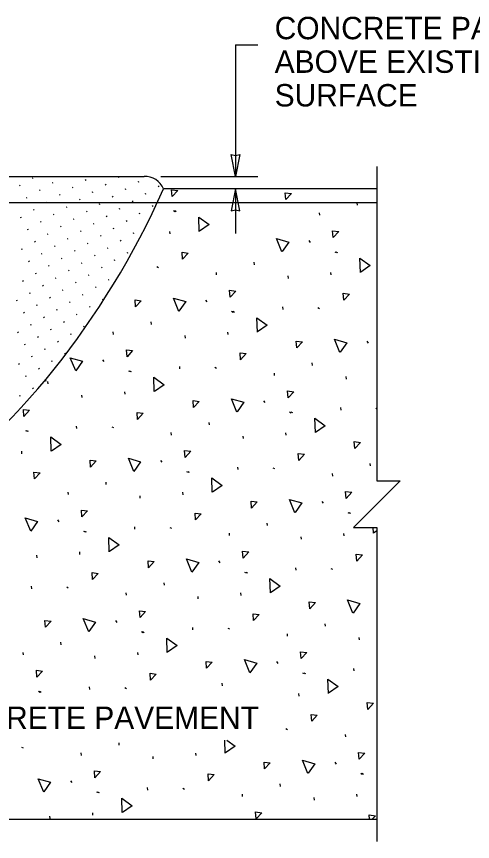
# Model space of a CAD drawing. Extents: x 99862 to 104211, y 98939 to 105076.
# Drawn here: x 102390 to 102716, y 103789 to 104378 of the extents above; entities that cross this region are included whole.
import ezdxf

# ---------------------------------------------------------------- set-up
doc = ezdxf.new("R2010")
doc.units = 0
for name, color, linetype in [('Level 1', 7, 'Continuous'), ('Level 15', 7, 'Continuous'), ('Level 20', 7, 'Continuous'), ('Level 3', 7, 'Continuous'), ('Level 4', 7, 'Continuous'), ('Level 6', 7, 'Continuous')]:
    doc.layers.add(name, color=color, linetype=linetype)

msp = doc.modelspace()

# ---------------------------------------------------------------- linework, layer by layer
at = {"layer": 'Level 1'}
for p, q in [((102106.49, 104263.53), (102481.5, 104263.53)), ((102647.84, 104254.65), (102495.44, 104254.65))]:
    msp.add_line(p, q, dxfattribs=at)
for points in [[(102647.84, 104270.65), (102647.84, 104046.13), (102664.55, 104046.13), (102631.14, 104012.73), (102647.84, 104012.73), (102647.84, 103788.62)], [(100169.63, 103804.62), (100694.77, 103804.62), (102647.84, 103804.62)]]:
    msp.add_lwpolyline(points, dxfattribs=at)
msp.add_arc((102481.79, 104248.62), 14.92, 23.84243, 91.13462, dxfattribs=at)
msp.add_ellipse((102063.85, 104535.63), major_axis=(0, -590.4), ratio=0.83118, start_param=0, end_param=1.074783, dxfattribs=at)
msp.add_ellipse((102063.85, 104535.63), major_axis=(0, -590.4), ratio=0.83118, start_param=0, end_param=1.074783, dxfattribs=at)
at = {"layer": 'Level 15'}
for p, q in [((102546.8, 104357.47), (102546.8, 104263.53)), ((102546.8, 104357.47), (102562.8, 104357.47)), ((102546.8, 104254.65), (102546.8, 104222.65))]:
    msp.add_line(p, q, dxfattribs=at)
for points in [[(102546.8, 104263.53), (102543.72, 104279.26), (102546.8, 104278.53), (102549.89, 104279.26)], [(102546.8, 104254.65), (102543.72, 104238.92), (102546.8, 104239.65), (102549.89, 104238.92)]]:
    msp.add_lwpolyline(points, close=True, dxfattribs=at)
msp.add_lwpolyline([(102493.5, 104263.53), (102537.23, 104263.53), (102562.8, 104263.53)], dxfattribs=at)
at = {"layer": 'Level 3'}
for p, q in [((102401.68, 104262.19), (102402.29, 104262.54)), ((102463.02, 104262.96), (102463.62, 104263.31)), ((102392.41, 104256.84), (102393.02, 104257.19)), ((102415.95, 104258.88), (102416.55, 104259.23)), ((102439.48, 104260.92), (102440.09, 104261.27)), ((102453.75, 104257.61), (102454.36, 104257.96)), ((102477.29, 104259.65), (102477.89, 104260)), ((102491.55, 104256.34), (102492.16, 104256.69)), ((102406.68, 104253.53), (102407.29, 104253.88)), ((102430.21, 104255.57), (102430.82, 104255.92)), ((102444.48, 104252.26), (102445.09, 104252.61)), ((102468.02, 104254.3), (102468.62, 104254.65)), ((102482.29, 104250.99), (102482.89, 104251.34)), ((102397.41, 104248.18), (102398.02, 104248.53)), ((102411.68, 104244.87), (102412.29, 104245.22)), ((102420.95, 104250.22), (102421.55, 104250.57)), ((102435.21, 104246.91), (102435.82, 104247.26)), ((102458.75, 104248.95), (102459.36, 104249.3)), ((102473.02, 104245.64), (102473.62, 104245.99)), ((102402.41, 104239.52), (102403.02, 104239.87)), ((102425.95, 104241.56), (102426.55, 104241.91)), ((102449.48, 104243.6), (102450.09, 104243.95)), ((102463.75, 104240.29), (102464.36, 104240.64)), ((102487.29, 104242.33), (102487.89, 104242.68)), ((102393.14, 104234.17), (102393.75, 104234.52)), ((102416.68, 104236.21), (102417.29, 104236.56)), ((102430.95, 104232.9), (102431.55, 104233.25)), ((102440.21, 104238.25), (102440.82, 104238.6)), ((102454.48, 104234.94), (102455.09, 104235.29)), ((102478.02, 104236.98), (102478.62, 104237.33)), ((102407.41, 104230.86), (102408.02, 104231.21)), ((102421.68, 104227.55), (102422.29, 104227.9)), ((102445.21, 104229.59), (102445.82, 104229.94)), ((102468.75, 104231.63), (102469.36, 104231.98)), ((102398.14, 104225.51), (102398.75, 104225.86)), ((102412.41, 104222.2), (102413.02, 104222.55)), ((102435.95, 104224.24), (102436.55, 104224.59)), ((102450.21, 104220.93), (102450.82, 104221.28)), ((102459.48, 104226.28), (102460.09, 104226.63)), ((102473.75, 104222.97), (102474.36, 104223.32)), ((102403.14, 104216.85), (102403.75, 104217.2)), ((102426.68, 104218.89), (102427.29, 104219.24)), ((102440.95, 104215.58), (102441.55, 104215.93)), ((102464.48, 104217.62), (102465.09, 104217.97)), ((102393.88, 104211.49), (102394.48, 104211.84)), ((102417.41, 104213.54), (102418.02, 104213.89)), ((102431.68, 104210.23), (102432.29, 104210.58)), ((102455.21, 104212.27), (102455.82, 104212.62)), ((102408.14, 104208.19), (102408.75, 104208.54)), ((102422.41, 104204.88), (102423.02, 104205.23)), ((102445.95, 104206.92), (102446.55, 104207.27)), ((102460.21, 104203.61), (102460.82, 104203.96)), ((102469.48, 104208.96), (102470.09, 104209.31)), ((102398.88, 104202.83), (102399.48, 104203.18)), ((102413.14, 104199.53), (102413.75, 104199.88)), ((102436.68, 104201.57), (102437.29, 104201.92)), ((102450.95, 104198.26), (102451.55, 104198.61)), ((102403.88, 104194.17), (102404.48, 104194.52)), ((102427.41, 104196.22), (102428.02, 104196.57)), ((102441.68, 104192.91), (102442.29, 104193.26)), ((102394.61, 104188.82), (102395.21, 104189.17)), ((102408.88, 104185.51), (102409.48, 104185.86)), ((102418.14, 104190.86), (102418.75, 104191.21)), ((102432.41, 104187.56), (102433.02, 104187.91)), ((102455.95, 104189.6), (102456.55, 104189.95)), ((102399.61, 104180.16), (102400.21, 104180.51)), ((102423.14, 104182.2), (102423.75, 104182.55)), ((102446.68, 104184.25), (102447.29, 104184.6)), ((102390.34, 104174.81), (102390.95, 104175.16)), ((102413.88, 104176.85), (102414.48, 104177.2)), ((102437.41, 104178.89), (102438.02, 104179.24)), ((102451.68, 104175.59), (102452.29, 104175.94)), ((102404.61, 104171.5), (102405.21, 104171.85)), ((102418.88, 104168.19), (102419.48, 104168.54)), ((102428.14, 104173.54), (102428.75, 104173.89)), ((102442.41, 104170.23), (102443.02, 104170.58)), ((102395.34, 104166.15), (102395.95, 104166.5)), ((102409.61, 104162.84), (102410.21, 104163.19)), ((102433.14, 104164.88), (102433.75, 104165.23)), ((102400.34, 104157.49), (102400.95, 104157.84)), ((102423.88, 104159.53), (102424.48, 104159.88)), ((102438.14, 104156.22), (102438.75, 104156.57)), ((102391.07, 104152.14), (102391.68, 104152.49)), ((102414.61, 104154.18), (102415.21, 104154.53)), ((102428.88, 104150.87), (102429.48, 104151.22)), ((102405.34, 104148.83), (102405.95, 104149.18)), ((102419.61, 104145.52), (102420.21, 104145.87)), ((102396.07, 104143.48), (102396.68, 104143.83)), ((102410.34, 104140.17), (102410.95, 104140.52)), ((102401.07, 104134.82), (102401.68, 104135.17)), ((102424.61, 104136.86), (102425.21, 104137.21)), ((102391.81, 104129.47), (102392.41, 104129.82)), ((102415.34, 104131.51), (102415.95, 104131.86)), ((102396.81, 104120.81), (102397.41, 104121.16)), ((102406.07, 104126.16), (102406.68, 104126.51)), ((102411.07, 104117.5), (102411.68, 104117.85)), ((102401.81, 104112.15), (102402.41, 104112.5)), ((102392.54, 104106.8), (102393.14, 104107.15))]:
    msp.add_line(p, q, dxfattribs=at)
at = {"layer": 'Level 4'}
for p, q in [((102634.02, 104242.98), (102633.83, 104244.72)), ((102502.55, 104239.09), (102503.7, 104238.52)), ((102503.37, 104239.09), (102504.51, 104238.52)), ((102607, 104235.79), (102606.81, 104237.53)), ((102500.05, 104222.44), (102499.87, 104224.18)), ((102599.14, 104217.69), (102600.09, 104216.4)), ((102617.71, 104209.77), (102618.85, 104209.21)), ((102618.52, 104209.78), (102619.67, 104209.21)), ((102490.55, 104199.12), (102491.7, 104198.55)), ((102560.34, 104200.44), (102560.15, 104202.18)), ((102533.32, 104193.25), (102533.13, 104194.99)), ((102584.64, 104190.68), (102584.45, 104192.42)), ((102615.21, 104193.13), (102615.03, 104194.87)), ((102525.46, 104175.15), (102526.41, 104173.86)), ((102580.8, 104168.55), (102580.62, 104170.29)), ((102605.71, 104169.81), (102606.86, 104169.24)), ((102544.03, 104167.24), (102545.18, 104166.67)), ((102544.85, 104167.24), (102545.99, 104166.67)), ((102486.66, 104157.9), (102486.48, 104159.64)), ((102459.64, 104150.71), (102459.46, 104152.45)), ((102541.54, 104150.6), (102541.35, 104152.34)), ((102510.96, 104148.14), (102510.77, 104149.88)), ((102640.62, 104145.84), (102641.57, 104144.55)), ((102451.78, 104132.62), (102452.74, 104131.32)), ((102507.13, 104126.01), (102506.94, 104127.75)), ((102532.03, 104127.27), (102533.18, 104126.7)), ((102601.82, 104128.59), (102601.64, 104130.33)), ((102470.35, 104124.7), (102471.5, 104124.13)), ((102471.17, 104124.7), (102472.32, 104124.14)), ((102574.8, 104121.4), (102574.62, 104123.14)), ((102412.98, 104115.37), (102412.8, 104117.11)), ((102626.12, 104118.83), (102625.93, 104120.57)), ((102467.86, 104108.06), (102467.67, 104109.8)), ((102437.28, 104105.61), (102437.1, 104107.35)), ((102566.94, 104103.31), (102567.89, 104102.01)), ((102622.28, 104096.7), (102622.1, 104098.44)), ((102647.19, 104097.96), (102647.84, 104097.64)), ((102585.51, 104095.39), (102586.66, 104094.82)), ((102586.33, 104095.39), (102587.48, 104094.83)), ((102528.14, 104086.06), (102527.96, 104087.8)), ((102396.67, 104082.16), (102397.82, 104081.59)), ((102397.49, 104082.17), (102398.64, 104081.6)), ((102433.45, 104083.48), (102433.26, 104085.21)), ((102458.36, 104084.73), (102459.51, 104084.16)), ((102501.12, 104078.87), (102500.94, 104080.61)), ((102583.02, 104078.75), (102582.83, 104080.49)), ((102552.44, 104076.3), (102552.26, 104078.04)), ((102394.18, 104065.52), (102394, 104067.26)), ((102493.26, 104060.77), (102494.22, 104059.47)), ((102643.3, 104056.75), (102643.12, 104058.49)), ((102511.83, 104052.85), (102512.98, 104052.28)), ((102512.65, 104052.86), (102513.8, 104052.29)), ((102548.61, 104054.16), (102548.42, 104055.9)), ((102573.52, 104055.42), (102574.66, 104054.85)), ((102616.28, 104049.55), (102616.1, 104051.29)), ((102454.47, 104043.52), (102454.28, 104045.26)), ((102427.45, 104036.33), (102427.26, 104038.07)), ((102478.76, 104033.76), (102478.58, 104035.5)), ((102509.34, 104036.21), (102509.16, 104037.95)), ((102608.42, 104031.46), (102609.38, 104030.16)), ((102626.99, 104023.54), (102628.14, 104022.97)), ((102627.81, 104023.55), (102628.96, 104022.98)), ((102419.59, 104018.23), (102420.54, 104016.94)), ((102569.62, 104014.21), (102569.44, 104015.95)), ((102438.16, 104010.31), (102439.3, 104009.75)), ((102438.97, 104010.32), (102440.12, 104009.75)), ((102474.93, 104011.63), (102474.75, 104013.37)), ((102499.84, 104012.88), (102500.99, 104012.32)), ((102542.6, 104007.02), (102542.42, 104008.76)), ((102593.92, 104004.45), (102593.74, 104006.19)), ((102624.5, 104006.9), (102624.31, 104008.64)), ((102405.09, 103991.22), (102404.9, 103992.96)), ((102435.66, 103993.67), (102435.48, 103995.41)), ((102534.75, 103988.92), (102535.7, 103987.63)), ((102553.31, 103981), (102554.46, 103980.44)), ((102554.13, 103981.01), (102555.28, 103980.44)), ((102590.09, 103982.32), (102589.9, 103984.06)), ((102615, 103983.57), (102616.15, 103983.01)), ((102401.25, 103969.09), (102401.07, 103970.83)), ((102426.16, 103970.35), (102427.31, 103969.78)), ((102495.95, 103971.67), (102495.76, 103973.41)), ((102468.93, 103964.48), (102468.74, 103966.22)), ((102520.24, 103961.91), (102520.06, 103963.65)), ((102550.82, 103964.36), (102550.64, 103966.1)), ((102461.07, 103946.38), (102462.02, 103945.09)), ((102479.64, 103938.47), (102480.79, 103937.9)), ((102480.46, 103938.47), (102481.6, 103937.9)), ((102516.41, 103939.78), (102516.23, 103941.52)), ((102541.32, 103941.04), (102542.47, 103940.47)), ((102611.11, 103942.36), (102610.92, 103944.1)), ((102584.09, 103935.17), (102583.9, 103936.91)), ((102635.4, 103932.6), (102635.22, 103934.34)), ((102422.27, 103929.13), (102422.09, 103930.87)), ((102395.25, 103921.94), (102395.07, 103923.68)), ((102446.57, 103919.37), (102446.38, 103921.11)), ((102477.14, 103921.82), (102476.96, 103923.56)), ((102576.23, 103917.07), (102577.18, 103915.78)), ((102594.8, 103909.16), (102595.94, 103908.59)), ((102595.61, 103909.16), (102596.76, 103908.59)), ((102631.57, 103910.47), (102631.39, 103912.21)), ((102442.73, 103897.24), (102442.55, 103898.98)), ((102467.64, 103898.5), (102468.79, 103897.93)), ((102537.43, 103899.82), (102537.24, 103901.56)), ((102405.96, 103895.93), (102407.11, 103895.36)), ((102406.78, 103895.93), (102407.93, 103895.37)), ((102592.3, 103892.51), (102592.12, 103894.25)), ((102582.8, 103869.19), (102583.95, 103868.62)), ((102625.57, 103863.32), (102625.38, 103865.06)), ((102393.97, 103855.96), (102395.11, 103855.39)), ((102463.75, 103857.29), (102463.57, 103859.03)), ((102436.73, 103850.09), (102436.55, 103851.83)), ((102518.63, 103849.98), (102518.44, 103851.72)), ((102488.05, 103847.53), (102487.87, 103849.26)), ((102617.71, 103845.22), (102618.66, 103843.93)), ((102636.28, 103837.31), (102637.43, 103836.74)), ((102637.1, 103837.31), (102638.24, 103836.74)), ((102428.87, 103832), (102429.83, 103830.7)), ((102484.22, 103825.39), (102484.03, 103827.13)), ((102509.12, 103826.65), (102510.27, 103826.08)), ((102578.91, 103827.98), (102578.73, 103829.71)), ((102447.44, 103824.08), (102448.59, 103823.51)), ((102448.26, 103824.09), (102449.41, 103823.52)), ((102551.89, 103820.78), (102551.71, 103822.52)), ((102633.78, 103820.67), (102633.6, 103822.41)), ((102603.21, 103818.21), (102603.02, 103819.95)), ((102444.95, 103807.44), (102444.76, 103809.18)), ((102414.37, 103804.99), (102414.19, 103806.73))]:
    msp.add_line(p, q, dxfattribs=at)
for points in [[(102501.47, 104249.13), (102501.09, 104254.04), (102505.5, 104253.51), (102501.47, 104249.13)], [(102582.69, 104246.98), (102582.31, 104251.89), (102586.72, 104251.36), (102582.69, 104246.98)], [(102520.95, 104224.26), (102520.58, 104234.5), (102527.98, 104229.14), (102521.11, 104224.35)], [(102616.63, 104219.82), (102616.25, 104224.73), (102620.66, 104224.2), (102616.63, 104219.82)], [(102579.97, 104209.65), (102576.11, 104219.15), (102584.91, 104216.64), (102580.08, 104209.79)], [(102509.01, 104204.44), (102508.64, 104209.35), (102513.05, 104208.82), (102509.01, 104204.44)], [(102636.11, 104194.95), (102635.74, 104205.19), (102643.14, 104199.82), (102636.27, 104195.04)], [(102542.95, 104177.28), (102542.58, 104182.19), (102546.98, 104181.66), (102542.95, 104177.28)], [(102624.17, 104175.13), (102623.8, 104180.04), (102628.2, 104179.51), (102624.17, 104175.13)], [(102475.4, 104170.38), (102475.03, 104175.29), (102479.43, 104174.76), (102475.4, 104170.38)], [(102506.29, 104167.12), (102502.44, 104176.61), (102511.23, 104174.1), (102506.41, 104167.25)], [(102562.44, 104152.41), (102562.06, 104162.65), (102569.46, 104157.29), (102562.59, 104152.5)], [(102590.56, 104141.07), (102590.18, 104145.98), (102594.59, 104145.45), (102590.56, 104141.07)], [(102621.45, 104137.81), (102617.59, 104147.3), (102626.39, 104144.79), (102621.56, 104137.94)], [(102469.27, 104134.74), (102468.9, 104139.65), (102473.31, 104139.12), (102469.27, 104134.74)], [(102432.62, 104124.58), (102428.76, 104134.07), (102437.55, 104131.57), (102432.73, 104124.72)], [(102550.49, 104132.59), (102550.12, 104137.51), (102554.53, 104136.97), (102550.49, 104132.59)], [(102488.76, 104109.87), (102488.38, 104120.11), (102495.79, 104114.75), (102488.91, 104109.96)], [(102584.43, 104105.43), (102584.06, 104110.34), (102588.47, 104109.81), (102584.43, 104105.43)], [(102516.88, 104098.53), (102516.51, 104103.44), (102520.91, 104102.91), (102516.88, 104098.53)], [(102547.77, 104095.27), (102543.92, 104104.76), (102552.71, 104102.26), (102547.89, 104095.4)], [(102395.6, 104092.2), (102395.22, 104097.11), (102399.63, 104096.58), (102395.6, 104092.2)], [(102476.82, 104090.06), (102476.44, 104094.97), (102480.85, 104094.44), (102476.82, 104090.06)], [(102603.92, 104080.56), (102603.54, 104090.8), (102610.95, 104085.44), (102604.07, 104080.65)], [(102415.08, 104067.33), (102414.71, 104077.58), (102422.11, 104072.21), (102415.24, 104067.42)], [(102632.04, 104069.22), (102631.67, 104074.13), (102636.07, 104073.6), (102632.04, 104069.22)], [(102474.1, 104052.73), (102470.24, 104062.23), (102479.03, 104059.72), (102474.21, 104052.87)], [(102510.76, 104062.89), (102510.38, 104067.8), (102514.79, 104067.27), (102510.76, 104062.89)], [(102591.98, 104060.75), (102591.6, 104065.66), (102596.01, 104065.13), (102591.98, 104060.75)], [(102443.2, 104055.99), (102442.83, 104060.9), (102447.24, 104060.37), (102443.2, 104055.99)], [(102403.14, 104047.52), (102402.76, 104052.43), (102407.17, 104051.9), (102403.14, 104047.52)], [(102530.24, 104038.02), (102529.86, 104048.27), (102537.27, 104042.9), (102530.39, 104038.11)], [(102589.26, 104023.42), (102585.4, 104032.92), (102594.19, 104030.41), (102589.37, 104023.56)], [(102625.91, 104033.58), (102625.54, 104038.49), (102629.95, 104037.96), (102625.91, 104033.58)], [(102558.36, 104026.68), (102557.99, 104031.59), (102562.4, 104031.06), (102558.36, 104026.68)], [(102437.08, 104020.36), (102436.7, 104025.27), (102441.11, 104024.74), (102437.08, 104020.36)], [(102518.3, 104018.21), (102517.92, 104023.12), (102522.33, 104022.59), (102518.3, 104018.21)], [(102400.42, 104010.19), (102396.56, 104019.69), (102405.36, 104017.18), (102400.53, 104010.33)], [(102645.4, 104008.71), (102645.25, 104012.73)], [(102647.84, 104010.4), (102645.55, 104008.8)], [(102456.56, 103995.49), (102456.19, 104005.73), (102463.59, 104000.36), (102456.72, 103995.58)], [(102552.24, 103991.05), (102551.86, 103995.96), (102556.27, 103995.42), (102552.24, 103991.05)], [(102633.46, 103988.9), (102633.08, 103993.81), (102637.49, 103993.28), (102633.46, 103988.9)], [(102484.69, 103984.14), (102484.31, 103989.05), (102488.72, 103988.52), (102484.69, 103984.14)], [(102515.58, 103980.88), (102511.72, 103990.38), (102520.51, 103987.87), (102515.69, 103981.02)], [(102444.62, 103975.67), (102444.25, 103980.58), (102448.65, 103980.05), (102444.62, 103975.67)], [(102571.72, 103966.18), (102571.35, 103976.42), (102578.75, 103971.05), (102571.88, 103966.26)], [(102599.84, 103954.83), (102599.47, 103959.74), (102603.88, 103959.21), (102599.84, 103954.83)], [(102630.74, 103951.57), (102626.88, 103961.07), (102635.67, 103958.56), (102630.85, 103951.71)], [(102478.56, 103948.51), (102478.18, 103953.42), (102482.59, 103952.89), (102478.56, 103948.51)], [(102559.78, 103946.36), (102559.4, 103951.27), (102563.81, 103950.74), (102559.78, 103946.36)], [(102411.01, 103941.61), (102410.63, 103946.52), (102415.04, 103945.98), (102411.01, 103941.61)], [(102441.9, 103938.35), (102438.04, 103947.84), (102446.84, 103945.33), (102442.02, 103938.48)], [(102498.04, 103923.64), (102497.67, 103933.88), (102505.07, 103928.52), (102498.2, 103923.73)], [(102593.72, 103919.2), (102593.34, 103924.11), (102597.75, 103923.58), (102593.72, 103919.2)], [(102526.17, 103912.29), (102525.79, 103917.21), (102530.2, 103916.67), (102526.17, 103912.29)], [(102557.06, 103909.04), (102553.2, 103918.53), (102562, 103916.02), (102557.17, 103909.17)], [(102404.88, 103905.97), (102404.51, 103910.88), (102408.92, 103910.35), (102404.88, 103905.97)], [(102486.1, 103903.82), (102485.73, 103908.73), (102490.14, 103908.2), (102486.1, 103903.82)], [(102613.2, 103894.33), (102612.83, 103904.57), (102620.23, 103899.21), (102613.36, 103894.42)], [(102641.33, 103882.98), (102640.95, 103887.9), (102645.36, 103887.36), (102641.33, 103882.98)], [(102601.26, 103874.51), (102600.89, 103879.42), (102605.29, 103878.89), (102601.26, 103874.51)], [(102539.53, 103851.79), (102539.19, 103860.98)], [(102540.6, 103860.98), (102546.55, 103856.67), (102539.68, 103851.88)], [(102635.2, 103847.35), (102634.82, 103852.26), (102639.23, 103851.73), (102635.2, 103847.35)], [(102567.65, 103840.45), (102567.27, 103845.36), (102571.68, 103844.83), (102567.65, 103840.45)], [(102598.54, 103837.19), (102594.69, 103846.68), (102603.48, 103844.17), (102598.66, 103837.32)], [(102446.36, 103834.12), (102445.99, 103839.03), (102450.4, 103838.5), (102446.36, 103834.12)], [(102409.71, 103823.96), (102405.85, 103833.46), (102414.64, 103830.95), (102409.82, 103824.1)], [(102527.58, 103831.97), (102527.21, 103836.89), (102531.62, 103836.35), (102527.58, 103831.97)], [(102465.85, 103809.25), (102465.47, 103819.49), (102472.88, 103814.13), (102466, 103809.34)], [(102561.52, 103804.81), (102561.15, 103809.72), (102565.56, 103809.19), (102561.52, 103804.81)], [(102642.59, 103804.62), (102642.37, 103807.58), (102646.78, 103807.04), (102644.54, 103804.62)]]:
    msp.add_lwpolyline(points, dxfattribs=at)
at = {"layer": 'Level 6'}
msp.add_line((102647.84, 104244.65), (101394.64, 104244.65), dxfattribs=at)

# ---------------------------------------------------------------- texts
at = {"layer": 'Level 20'}
for s, p in [('CONCRETE PATCH MATERIAL ', (102574.8, 104361.47)), ('ABOVE EXISTING CONCRETE ', (102574.8, 104337.47)), ('SURFACE', (102574.8, 104313.47)), ('EXISTING CEMENT CONCRETE PAVEMENT', (102117.78, 103868.98))]:
    msp.add_text(s, height=16, dxfattribs=at).set_placement(p)

doc.saveas('drawing.dxf')
